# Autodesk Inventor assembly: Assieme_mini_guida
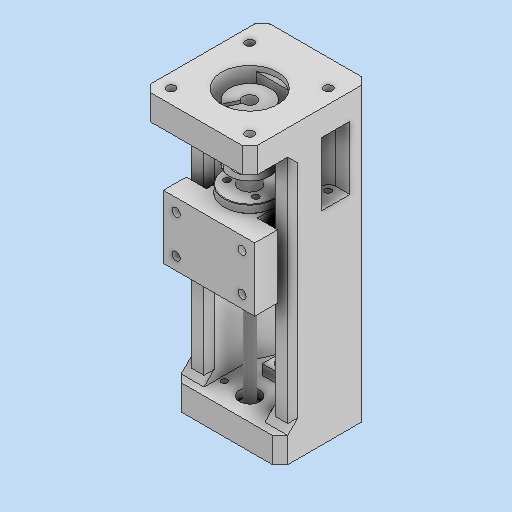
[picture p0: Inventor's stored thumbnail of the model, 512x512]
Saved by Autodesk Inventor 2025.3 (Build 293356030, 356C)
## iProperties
Created: 2025-12
Part Number: Assieme_mini_guida
Document SubType Name: Assembly
Designer: Ryzen5700u
Author: Ryzen5700u
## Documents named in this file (9)
- C:\Users\R5800u\Desktop\guida small\Assieme_mini_guida.iam
- C:\Users\R5800u\Desktop\guida small\t4 nut dado.ipt
- C:\Users\R5800u\Desktop\guida small\barra T4.ipt
- C:\Users\R5800u\Desktop\guida small\nema17_23mm.ipt
- C:\Users\R5800u\Desktop\guida small\blocco_barre.ipt
- C:\Users\R5800u\Desktop\guida small\frame.ipt
- C:\Users\R5800u\Desktop\guida small\barra_6mm.ipt
- C:\Users\R5800u\Desktop\guida small\dado_barra.ipt
- C:\Users\R5800u\Documents\Inventor\Content Center Files\R2025\it-IT\BS 290 SKF(30)\BS 290 SKF - SKF 604.ipt
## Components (8 placed, 8 different names)
1. t4 nut dado:1 — Coincidente:1, Angolo:3, Coincidente:9, Allineato:2
2. barra T4:1 — Coincidente:1, Coincidente:2, Coincidente:3, Coincidente:4
3. nema17_23mm:1 — Coincidente:2, Coincidente:3, Angolo:1, Coincidente:5, Coincidente:6, Angolo:2, Coincidente:8, Allineato:1, Angolo:3
4. blocco_barre:1 — Coincidente:4, Coincidente:5, Coincidente:9
5. barra_6mm:1
6. frame:1 — Coincidente:6, Angolo:2, Coincidente:8, Rotazionale:2
7. dado_barra:1 — Allineato:2
8. BS 290 SKF 604:1 — Rotazionale:2
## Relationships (14: Mate 8, Angle 3, Flush 2, RevoluteJoint 1)
- Coincidente:1 [Mate]: t4 nut dado:1 ↔ barra T4:1
- Coincidente:2 [Mate]: barra T4:1 ↔ nema17_23mm:1
- Coincidente:3 [Mate]: barra T4:1 ↔ nema17_23mm:1
- Angolo:1 [Angle]: nema17_23mm:1
- Coincidente:4 [Mate]: barra T4:1 ↔ blocco_barre:1
- Coincidente:5 [Mate]: nema17_23mm:1 ↔ blocco_barre:1
- Coincidente:6 [Mate]: nema17_23mm:1 ↔ frame:1
- Angolo:2 [Angle]: nema17_23mm:1 ↔ frame:1
- Coincidente:8 [Mate]: nema17_23mm:1 ↔ frame:1
- Allineato:1 [Flush]: nema17_23mm:1
- Angolo:3 [Angle]: t4 nut dado:1 ↔ nema17_23mm:1
- Coincidente:9 [Mate]: t4 nut dado:1 ↔ blocco_barre:1
- Allineato:2 [Flush]: t4 nut dado:1 ↔ dado_barra:1
- Rotazionale:2 [RevoluteJoint]: frame:1 ↔ BS 290 SKF 604:1
